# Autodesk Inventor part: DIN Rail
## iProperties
Created: 2009-09
Part Number: DIN Rail
Material: Steel, Mild
Document SubType Name: Modeling
Designer: TGH
Density: 7.86 g/cm^3
Mass: 48.6095 g
Surface Area: 130.188 cm^2
Volume: 6.18442 cm^3
Length: 150,0 mm
Title: DIN RAIL
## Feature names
1. Plate [Extrusion]
2. Holes [Extrusion]
3. Hole Pattern [Rectangular Pattern]
